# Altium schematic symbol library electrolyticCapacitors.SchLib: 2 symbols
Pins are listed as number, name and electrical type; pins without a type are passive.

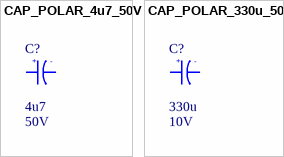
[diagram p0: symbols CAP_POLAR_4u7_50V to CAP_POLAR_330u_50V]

## CAP_POLAR_4u7_50V
designator C?, comment Voltage: 50V  (hidden comment: 4u7)
SMD Aluminium Electrolytic Capacitor, Radial Can - SMD, 4.7 µF, 50 V, 5000 hours @ 105°C, Polar; Manufacturer: Wurth Elektrinik; Mfr Part Num: 865230642008
footprint 865230642008 (SMD Aluminium Electrolytic Capacitor, Radial Can - SMD, 4.7 µF, 50 V, 5000 hours @ 105°C, Polar)
pins: 1 Pin 1, 2 Pin 2

## CAP_POLAR_330u_50V
designator C?, comment Voltage: 10V  (hidden comment: 330u)
SMD Aluminium Electrolytic Capacitor, Radial Can - SMD, 4.7 µF, 50 V, 5000 hours @ 105°C, Polar; Manufacturer: Kemet; Mfr Part Num: EDK337M010A9MAA
footprint CAPAE10083X105M (Aluminum Electrolytic Capacitor, Body 8.30x8.30x10.50mm, IPC Low Density)
pins: 1 Pin 1, 2 Pin 2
